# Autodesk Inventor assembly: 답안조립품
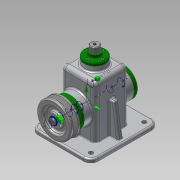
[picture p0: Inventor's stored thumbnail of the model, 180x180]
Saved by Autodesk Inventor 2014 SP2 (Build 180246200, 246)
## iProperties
Created: 2016-08
Part Number: 답안조립품
Document SubType Name: Assembly
Designer: user
Author: user
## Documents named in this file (19)
- C:\Users\user\Desktop\460820V1019\답안조립품.iam
- C:\Users\user\Desktop\460820V1019\본체.ipt
- C:\Users\user\Desktop\460820V1019\앞커버.ipt
- C:\Users\user\Desktop\460820V1019\뒤커버.ipt
- C:\Users\user\Desktop\460820V1019\볼트 M4 x 10.ipt
- C:\Users\user\Desktop\460820V1019\베어링 15 x 35 x 11.ipt
- C:\Users\user\Desktop\460820V1019\편심축.ipt
- C:\Users\user\Desktop\460820V1019\멈춤링 15 x 1.ipt
- C:\Users\user\Desktop\460820V1019\오일실 15 25 7.ipt
- C:\Users\user\Desktop\460820V1019\키 5 x 5 x 14.ipt
- C:\Users\user\Desktop\460820V1019\와셔.ipt
- C:\Users\user\Desktop\460820V1019\V-벨트풀리.ipt
- C:\Users\user\Desktop\460820V1019\볼트 M6 x 12.ipt
- C:\Users\user\Desktop\460820V1019\링크.ipt
- C:\Users\user\Desktop\460820V1019\고정핀.ipt
- C:\Users\user\Desktop\460820V1019\멈춤링 6 x 5.ipt
- C:\Users\user\Desktop\460820V1019\슬라이드바.ipt
- C:\Users\user\Desktop\460820V1019\상부부시.ipt
- C:\Users\user\Desktop\460820V1019\볼트 M3 x 8.ipt
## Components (15 placed, 5 different names)
1. V-벨트풀리:1 — 각도:1
2. ISO 4018 M6 x 12:1
3. 고정핀:1
4. ISO 4762 M4 x 10:2 — 강체:1
5. ISO 4762 M4 x 10:3
6. ISO 4762 M4 x 10:4
7. ISO 4762 M4 x 10:5
8. ISO 4762 M4 x 10:1 — 강체:2
9. ISO 4762 M4 x 10:6
10. ISO 4762 M4 x 10:7
11. ISO 4762 M4 x 10:8
12. ISO 4762 M3 x 8:1 — 강체:3
13. ISO 4762 M3 x 8:2
14. ISO 4762 M3 x 8:3
15. ISO 4762 M3 x 8:4
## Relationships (4: WeldJoint 3, Angle 1)
- 강체:1 [WeldJoint]: ISO 4762 M4 x 10:2
- 강체:2 [WeldJoint]: ISO 4762 M4 x 10:1
- 각도:1 [Angle]: V-벨트풀리:1
- 강체:3 [WeldJoint]: ISO 4762 M3 x 8:1
